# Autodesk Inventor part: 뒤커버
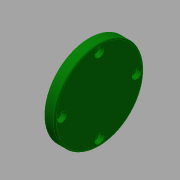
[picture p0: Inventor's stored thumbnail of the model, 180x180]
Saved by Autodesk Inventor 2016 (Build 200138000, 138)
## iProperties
Created: 2015-09
Part Number: 뒤커버
Material: 알루미늄 6061
Document SubType Name: Modeling
Designer: mduedu
Density: 2.71 g/cm^3
Mass: 54.0417 g
Surface Area: 84.9688 cm^2
Volume: 19.9416 cm^3
Appearance: 진녹색
Author: mduedu
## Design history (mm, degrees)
sketch "스케치1"
  geometry: L1 (-15.5, 47)-(-15.5, 78); L2 (-15.5, 78)-(-22.5, 78); L3 (-22.5, 78)-(-22.5, 63); L4 (-28.5, 63)-(-28.5, 47); L5 (-79.5, 39.5)-(-79.5, 54.5) reference; L6 (48.5, 54.5)-(48.5, 39.5) reference; L7 (-79.5, 47)-(48.5, 47); L8 (-22.5, 63)-(-28.5, 63); L9 (-28.5, 47)-(-15.5, 47); 1 further point
  constraints: 14 end point, 4 midpoint, 3 parallel, 1 collinear, 1 point on line, 1 vertical
  dimensions: "d6" = 62 diameter of L2 L7; "d7" = 7 distance of L1.end L2.end; "d8" = 32 diameter of L3.end L7; "d32" = 13 distance between parallel lines of L1 L4
revolve "회전1" sketch "스케치1" stored, may be unused: angle "d4" = 90 deg
sketch "스케치4"
  geometry: C1 r 31 at (0, 0) reference; 2 further points
  constraints: 1 coincident
hole "구멍3" sketch "스케치4" at (0, 0) diameter "d33" = 22; stored, may be unused: countersink angle "d37" = 90 deg, drill point angle "d39" = 0 deg; dims "d34" = 6, "d35" = 4, "d36" = 2, "d38" = 8
fillet "모깎기4" dims "d40" = 1
chamfer "모따기2" distance "d41" = 1; stored, may be unused: second distance "d42" = 2, angle "d43" = 45 deg
sketch "스케치6" dims "d56" = 52
  geometry: C1 r 31 at (0, 0) reference; 5 further points
  constraints: 2 vertical alignment, 1 coincident, 7 other
  dimensions: "d59" = 360 deg dimension on C1.centre point (0, 26) (derived)
hole "구멍4" sketch "스케치6" at (0, 26), (-26, 0), (0, -26), (26, 0) diameter "d49" = 3.4; stored, may be unused: countersink angle "d53" = 90 deg, drill point angle "d55" = 0 deg; dims "d50" = 6, "d51" = 6.5, "d52" = 3.4, "d54" = 8
fillet "모깎기5" dims "d61" = 3
node "솔리드1"
node "참조1"
node "참조2"
